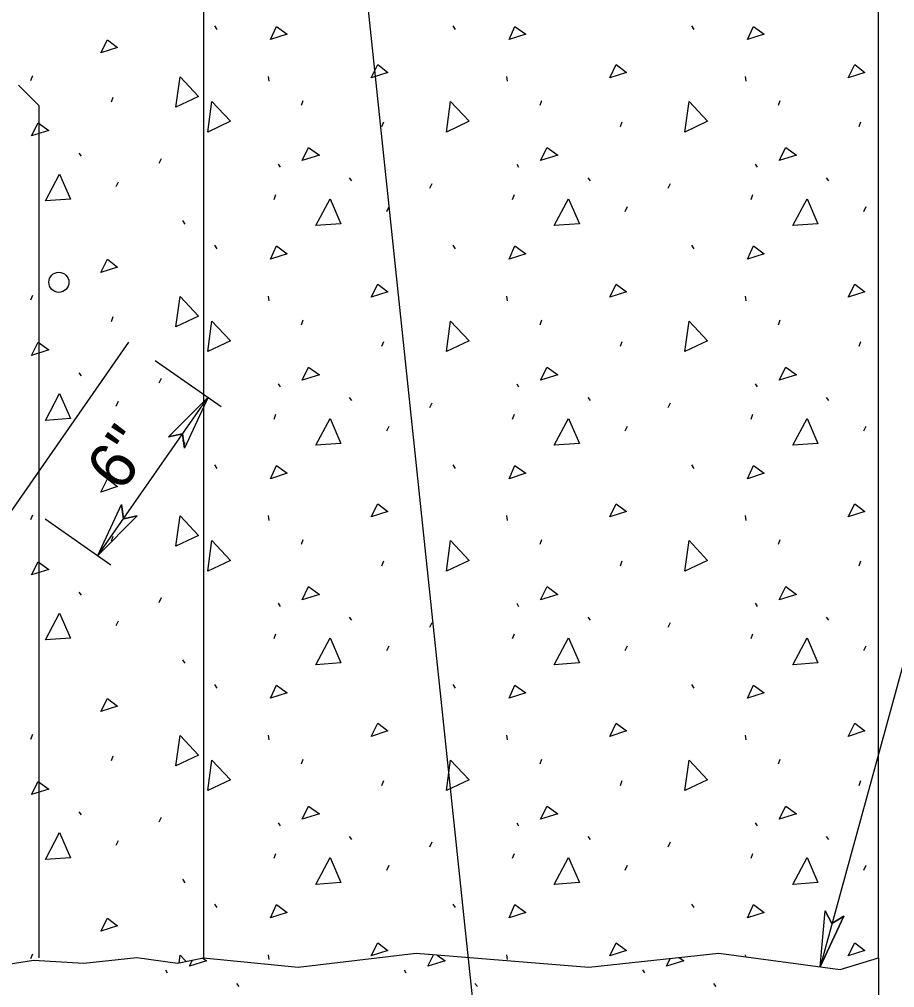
# Model space of a CAD drawing. Extents: x -26.5 to -19.2, y -3.6 to 6.6.
# Drawn here: x -23.351 to -22.216, y 1.707 to 2.961 of the extents above; entities that cross this region are included whole.
import ezdxf

# ---------------------------------------------------------------- set-up
doc = ezdxf.new("R2010")
doc.units = 0
for name, color, linetype in [('DETL-DIMS', 7, 'Continuous'), ('DETL-PATT', 7, 'Continuous'), ('Level 10', 7, 'Continuous'), ('Level 12', 7, 'Continuous'), ('SUBS-FOOT_P', 7, 'Continuous'), ('SUPR-RFRC', 7, 'Continuous')]:
    doc.layers.add(name, color=color, linetype=linetype)

msp = doc.modelspace()

# ---------------------------------------------------------------- linework, layer by layer
at = {"layer": 'DETL-DIMS'}
for p, q in [((-23.1061, 2.4717), (-23.1572, 2.4202)), ((-23.1061, 2.4717), (-23.1366, 2.4057)), ((-23.1572, 2.4202), (-23.1393, 2.4241)), ((-23.1393, 2.4241), (-23.1366, 2.4057)), ((-23.249, 2.2665), (-23.2185, 2.3325)), ((-23.2158, 2.3141), (-23.2185, 2.3325)), ((-23.249, 2.2665), (-23.1979, 2.318)), ((-23.1979, 2.318), (-23.2158, 2.3141)), ((-22.3128, 1.7338), (-22.3062, 1.8061)), ((-22.3128, 1.7338), (-22.2819, 1.7994)), ((-22.2975, 1.7897), (-22.3062, 1.8061)), ((-22.2819, 1.7994), (-22.2975, 1.7897))]:
    msp.add_line(p, q, dxfattribs=at)
for points in [[(-23.1572, 2.4202), (-23.1061, 2.4717), (-23.1366, 2.4057), (-23.1393, 2.4241)], [(-23.1979, 2.318), (-23.249, 2.2665), (-23.2185, 2.3325), (-23.2158, 2.3141)], [(-22.2819, 1.7994), (-22.3128, 1.7338), (-22.3062, 1.8061), (-22.2975, 1.7897)]]:
    msp.add_lwpolyline(points, close=True, dxfattribs=at)
at = {"layer": 'DETL-PATT'}
for p, q in [((-23.0979, 2.9528), (-23.0948, 2.9482)), ((-22.7887, 2.9528), (-22.7856, 2.9482)), ((-22.4795, 2.9528), (-22.4764, 2.9482)), ((-23.3356, 2.8821), (-23.3333, 2.8883)), ((-23.0283, 2.8871), (-23.0275, 2.8809)), ((-22.7191, 2.8871), (-22.7184, 2.8809)), ((-22.41, 2.8871), (-22.4092, 2.8809)), ((-23.2312, 2.8543), (-23.2289, 2.8605)), ((-22.985, 2.85), (-22.9827, 2.8562)), ((-22.6758, 2.85), (-22.6735, 2.8562)), ((-22.3667, 2.85), (-22.3644, 2.8562)), ((-22.8807, 2.8222), (-22.8784, 2.8284)), ((-22.5715, 2.8222), (-22.5692, 2.8284)), ((-22.2623, 2.8222), (-22.26, 2.8284)), ((-23.2737, 2.7879), (-23.2707, 2.784)), ((-23.1694, 2.7747), (-23.1663, 2.7809)), ((-23.0152, 2.7735), (-23.0128, 2.7696)), ((-22.706, 2.7735), (-22.7037, 2.7696)), ((-22.3968, 2.7735), (-22.3945, 2.7696)), ((-23.225, 2.7446), (-23.222, 2.7507)), ((-22.9232, 2.7557), (-22.9201, 2.7518)), ((-22.8188, 2.7426), (-22.8157, 2.7487)), ((-22.614, 2.7557), (-22.6109, 2.7518)), ((-22.5097, 2.7426), (-22.5066, 2.7487)), ((-22.3048, 2.7557), (-22.3017, 2.7518)), ((-23.0206, 2.7279), (-23.0183, 2.7341)), ((-22.7114, 2.7279), (-22.7091, 2.7341)), ((-22.4022, 2.7279), (-22.3999, 2.7341)), ((-22.8745, 2.7124), (-22.8714, 2.7186)), ((-22.5653, 2.7124), (-22.5622, 2.7186)), ((-22.2561, 2.7124), (-22.253, 2.7186)), ((-23.1393, 2.7005), (-23.1362, 2.6959)), ((-23.0979, 2.6684), (-23.0948, 2.6637)), ((-22.7887, 2.6684), (-22.7856, 2.6637)), ((-22.4795, 2.6684), (-22.4764, 2.6637)), ((-23.3356, 2.5977), (-23.3333, 2.6039)), ((-23.0283, 2.6027), (-23.0275, 2.5965)), ((-22.7191, 2.6027), (-22.7184, 2.5965)), ((-22.41, 2.6027), (-22.4092, 2.5965)), ((-23.2312, 2.5699), (-23.2289, 2.5761)), ((-22.985, 2.5656), (-22.9827, 2.5717)), ((-22.6758, 2.5656), (-22.6735, 2.5717)), ((-22.3667, 2.5656), (-22.3644, 2.5717)), ((-22.8807, 2.5377), (-22.8784, 2.5439)), ((-22.5715, 2.5377), (-22.5692, 2.5439)), ((-22.2623, 2.5377), (-22.26, 2.5439)), ((-23.2737, 2.5034), (-23.2707, 2.4995)), ((-23.1694, 2.4903), (-23.1663, 2.4965)), ((-23.0152, 2.489), (-23.0128, 2.4852)), ((-22.706, 2.489), (-22.7037, 2.4852)), ((-22.3968, 2.489), (-22.3945, 2.4852)), ((-22.9232, 2.4713), (-22.9201, 2.4674)), ((-22.614, 2.4713), (-22.6109, 2.4674)), ((-22.3048, 2.4713), (-22.3017, 2.4674)), ((-23.225, 2.4601), (-23.222, 2.4663)), ((-22.8188, 2.4581), (-22.8157, 2.4643)), ((-22.5097, 2.4581), (-22.5066, 2.4643)), ((-23.0206, 2.4434), (-23.0183, 2.4496)), ((-22.7114, 2.4434), (-22.7091, 2.4496)), ((-22.4022, 2.4434), (-22.3999, 2.4496)), ((-22.8745, 2.428), (-22.8714, 2.4342)), ((-22.5653, 2.428), (-22.5622, 2.4342)), ((-22.2561, 2.428), (-22.253, 2.4342)), ((-23.1393, 2.4161), (-23.1362, 2.4114)), ((-23.0979, 2.3839), (-23.0948, 2.3793)), ((-22.7887, 2.3839), (-22.7856, 2.3793)), ((-22.4795, 2.3839), (-22.4764, 2.3793)), ((-23.3356, 2.3133), (-23.3333, 2.3194)), ((-23.0283, 2.3182), (-23.0275, 2.312)), ((-22.7191, 2.3182), (-22.7184, 2.312)), ((-22.41, 2.3182), (-22.4092, 2.312)), ((-23.2312, 2.2854), (-23.2289, 2.2916)), ((-22.985, 2.2811), (-22.9827, 2.2873)), ((-22.6758, 2.2811), (-22.6735, 2.2873)), ((-22.3667, 2.2811), (-22.3644, 2.2873)), ((-22.8807, 2.2533), (-22.8784, 2.2595)), ((-22.5715, 2.2533), (-22.5692, 2.2595)), ((-22.2623, 2.2533), (-22.26, 2.2595)), ((-23.2737, 2.219), (-23.2707, 2.2151)), ((-23.1694, 2.2058), (-23.1663, 2.212)), ((-23.0152, 2.2046), (-23.0128, 2.2007)), ((-22.706, 2.2046), (-22.7037, 2.2007)), ((-22.3968, 2.2046), (-22.3945, 2.2007)), ((-22.9232, 2.1868), (-22.9201, 2.183)), ((-22.614, 2.1868), (-22.6109, 2.183)), ((-22.3048, 2.1868), (-22.3017, 2.183)), ((-23.225, 2.1757), (-23.222, 2.1819)), ((-22.8188, 2.1737), (-22.8157, 2.1799)), ((-22.5097, 2.1737), (-22.5066, 2.1799)), ((-23.0206, 2.159), (-23.0183, 2.1652)), ((-22.7114, 2.159), (-22.7091, 2.1652)), ((-22.4022, 2.159), (-22.3999, 2.1652)), ((-22.8745, 2.1435), (-22.8714, 2.1497)), ((-22.5653, 2.1435), (-22.5622, 2.1497)), ((-22.2561, 2.1435), (-22.253, 2.1497)), ((-23.1393, 2.1316), (-23.1362, 2.127)), ((-23.0979, 2.0995), (-23.0948, 2.0948)), ((-22.7887, 2.0995), (-22.7856, 2.0948)), ((-22.4795, 2.0995), (-22.4764, 2.0948)), ((-23.3356, 2.0288), (-23.3333, 2.035)), ((-23.0283, 2.0338), (-23.0275, 2.0276)), ((-22.7191, 2.0338), (-22.7184, 2.0276)), ((-22.41, 2.0338), (-22.4092, 2.0276)), ((-23.2312, 2.001), (-23.2289, 2.0072)), ((-22.985, 1.9967), (-22.9827, 2.0029)), ((-22.6758, 1.9967), (-22.6735, 2.0029)), ((-22.3667, 1.9967), (-22.3644, 2.0029)), ((-22.8807, 1.9688), (-22.8784, 1.975)), ((-22.5715, 1.9688), (-22.5692, 1.975)), ((-22.2623, 1.9688), (-22.26, 1.975)), ((-23.2737, 1.9345), (-23.2707, 1.9307)), ((-23.1694, 1.9214), (-23.1663, 1.9276)), ((-23.0152, 1.9202), (-23.0128, 1.9163)), ((-22.706, 1.9202), (-22.7037, 1.9163)), ((-22.3968, 1.9202), (-22.3945, 1.9163)), ((-23.225, 1.8912), (-23.222, 1.8974)), ((-22.9232, 1.9024), (-22.9201, 1.8985)), ((-22.8188, 1.8892), (-22.8157, 1.8954)), ((-22.614, 1.9024), (-22.6109, 1.8985)), ((-22.5097, 1.8892), (-22.5066, 1.8954)), ((-22.3048, 1.9024), (-22.3017, 1.8985)), ((-23.0206, 1.8746), (-23.0183, 1.8807)), ((-22.7114, 1.8746), (-22.7091, 1.8807)), ((-22.4022, 1.8746), (-22.3999, 1.8807)), ((-22.8745, 1.8591), (-22.8714, 1.8653)), ((-22.5653, 1.8591), (-22.5622, 1.8653)), ((-22.2561, 1.8591), (-22.253, 1.8653)), ((-23.1393, 1.8472), (-23.1362, 1.8425)), ((-23.0979, 1.815), (-23.0948, 1.8104)), ((-22.7887, 1.815), (-22.7856, 1.8104)), ((-22.4795, 1.815), (-22.4764, 1.8104)), ((-23.3356, 1.7444), (-23.3333, 1.7506)), ((-23.0283, 1.7493), (-23.0275, 1.7432)), ((-22.8211, 1.7345), (-22.8137, 1.7493)), ((-22.7191, 1.7493), (-22.7184, 1.7432)), ((-22.5119, 1.7345), (-22.507, 1.7444)), ((-22.41, 1.7493), (-22.4096, 1.7466)), ((-23.1303, 1.7345), (-23.1263, 1.7426)), ((-23.1612, 1.7299), (-23.1589, 1.726)), ((-22.852, 1.7299), (-22.8497, 1.726)), ((-22.5429, 1.7299), (-22.5405, 1.726)), ((-23.0692, 1.7121), (-23.0661, 1.7083)), ((-22.7601, 1.7121), (-22.757, 1.7083)), ((-22.4509, 1.7121), (-22.4478, 1.7083))]:
    msp.add_line(p, q, dxfattribs=at)
for points in [[(-23.0252, 2.935), (-23.0175, 2.952), (-23.0036, 2.942), (-23.0252, 2.935)], [(-22.716, 2.935), (-22.7083, 2.952), (-22.6944, 2.942), (-22.716, 2.935)], [(-22.4069, 2.935), (-22.3991, 2.952), (-22.3852, 2.942), (-22.4069, 2.935)], [(-23.2451, 2.9177), (-23.2366, 2.9347), (-23.2235, 2.9247), (-23.2451, 2.9177)], [(-22.8946, 2.8856), (-22.8861, 2.9026), (-22.8729, 2.8925), (-22.8946, 2.8856)], [(-22.5854, 2.8856), (-22.5769, 2.9026), (-22.5638, 2.8925), (-22.5854, 2.8856)], [(-22.2762, 2.8856), (-22.2677, 2.9026), (-22.2546, 2.8925), (-22.2762, 2.8856)], [(-23.1478, 2.8474), (-23.1423, 2.8868), (-23.1184, 2.8613), (-23.1478, 2.8474)], [(-23.1064, 2.8152), (-23.101, 2.8546), (-23.077, 2.8291), (-23.1064, 2.8152)], [(-22.7972, 2.8152), (-22.7918, 2.8546), (-22.7678, 2.8291), (-22.7972, 2.8152)], [(-22.488, 2.8152), (-22.4826, 2.8546), (-22.4586, 2.8291), (-22.488, 2.8152)], [(-23.3348, 2.8103), (-23.3263, 2.8273), (-23.3124, 2.8172), (-23.3348, 2.8103)], [(-22.9842, 2.7781), (-22.9757, 2.7951), (-22.9618, 2.7851), (-22.9842, 2.7781)], [(-22.6751, 2.7781), (-22.6666, 2.7951), (-22.6527, 2.7851), (-22.6751, 2.7781)], [(-22.3659, 2.7781), (-22.3574, 2.7951), (-22.3435, 2.7851), (-22.3659, 2.7781)], [(-23.317, 2.726), (-23.2985, 2.7608), (-23.2846, 2.7283), (-23.317, 2.726)], [(-22.9665, 2.6939), (-22.9479, 2.7286), (-22.934, 2.6962), (-22.9665, 2.6939)], [(-22.6573, 2.6939), (-22.6387, 2.7286), (-22.6248, 2.6962), (-22.6573, 2.6939)], [(-22.3481, 2.6939), (-22.3296, 2.7286), (-22.3157, 2.6962), (-22.3481, 2.6939)], [(-23.0252, 2.6506), (-23.0175, 2.6676), (-23.0036, 2.6575), (-23.0252, 2.6506)], [(-22.716, 2.6506), (-22.7083, 2.6676), (-22.6944, 2.6575), (-22.716, 2.6506)], [(-22.4069, 2.6506), (-22.3991, 2.6676), (-22.3852, 2.6575), (-22.4069, 2.6506)], [(-23.2451, 2.6333), (-23.2366, 2.6503), (-23.2235, 2.6402), (-23.2451, 2.6333)], [(-22.8946, 2.6011), (-22.8861, 2.6181), (-22.8729, 2.6081), (-22.8946, 2.6011)], [(-22.5854, 2.6011), (-22.5769, 2.6181), (-22.5638, 2.6081), (-22.5854, 2.6011)], [(-22.2762, 2.6011), (-22.2677, 2.6181), (-22.2546, 2.6081), (-22.2762, 2.6011)], [(-23.1478, 2.5629), (-23.1423, 2.6023), (-23.1184, 2.5768), (-23.1478, 2.5629)], [(-23.1064, 2.5308), (-23.101, 2.5702), (-23.077, 2.5447), (-23.1064, 2.5308)], [(-22.7972, 2.5308), (-22.7918, 2.5702), (-22.7678, 2.5447), (-22.7972, 2.5308)], [(-22.488, 2.5308), (-22.4826, 2.5702), (-22.4586, 2.5447), (-22.488, 2.5308)], [(-23.3348, 2.5258), (-23.3263, 2.5428), (-23.3124, 2.5328), (-23.3348, 2.5258)], [(-22.9842, 2.4937), (-22.9757, 2.5107), (-22.9618, 2.5006), (-22.9842, 2.4937)], [(-22.6751, 2.4937), (-22.6666, 2.5107), (-22.6527, 2.5006), (-22.6751, 2.4937)], [(-22.3659, 2.4937), (-22.3574, 2.5107), (-22.3435, 2.5006), (-22.3659, 2.4937)], [(-23.317, 2.4416), (-23.2985, 2.4764), (-23.2846, 2.4439), (-23.317, 2.4416)], [(-22.9665, 2.4094), (-22.9479, 2.4442), (-22.934, 2.4117), (-22.9665, 2.4094)], [(-22.6573, 2.4094), (-22.6387, 2.4442), (-22.6248, 2.4117), (-22.6573, 2.4094)], [(-22.3481, 2.4094), (-22.3296, 2.4442), (-22.3157, 2.4117), (-22.3481, 2.4094)], [(-23.0252, 2.3661), (-23.0175, 2.3831), (-23.0036, 2.3731), (-23.0252, 2.3661)], [(-22.716, 2.3661), (-22.7083, 2.3831), (-22.6944, 2.3731), (-22.716, 2.3661)], [(-22.4069, 2.3661), (-22.3991, 2.3831), (-22.3852, 2.3731), (-22.4069, 2.3661)], [(-23.2451, 2.3488), (-23.2366, 2.3658), (-23.2235, 2.3558), (-23.2451, 2.3488)], [(-22.8946, 2.3167), (-22.8861, 2.3337), (-22.8729, 2.3236), (-22.8946, 2.3167)], [(-22.5854, 2.3167), (-22.5769, 2.3337), (-22.5638, 2.3236), (-22.5854, 2.3167)], [(-22.2762, 2.3167), (-22.2677, 2.3337), (-22.2546, 2.3236), (-22.2762, 2.3167)], [(-23.1478, 2.2785), (-23.1423, 2.3179), (-23.1184, 2.2924), (-23.1478, 2.2785)], [(-23.1064, 2.2463), (-23.101, 2.2858), (-23.077, 2.2602), (-23.1064, 2.2463)], [(-22.7972, 2.2463), (-22.7918, 2.2858), (-22.7678, 2.2602), (-22.7972, 2.2463)], [(-22.488, 2.2463), (-22.4826, 2.2858), (-22.4586, 2.2602), (-22.488, 2.2463)], [(-23.3348, 2.2414), (-23.3263, 2.2584), (-23.3124, 2.2483), (-23.3348, 2.2414)], [(-22.9842, 2.2092), (-22.9757, 2.2262), (-22.9618, 2.2162), (-22.9842, 2.2092)], [(-22.6751, 2.2092), (-22.6666, 2.2262), (-22.6527, 2.2162), (-22.6751, 2.2092)], [(-22.3659, 2.2092), (-22.3574, 2.2262), (-22.3435, 2.2162), (-22.3659, 2.2092)], [(-23.317, 2.1571), (-23.2985, 2.1919), (-23.2846, 2.1594), (-23.317, 2.1571)], [(-22.9665, 2.125), (-22.9479, 2.1598), (-22.934, 2.1273), (-22.9665, 2.125)], [(-22.6573, 2.125), (-22.6387, 2.1598), (-22.6248, 2.1273), (-22.6573, 2.125)], [(-22.3481, 2.125), (-22.3296, 2.1598), (-22.3157, 2.1273), (-22.3481, 2.125)], [(-23.0252, 2.0817), (-23.0175, 2.0987), (-23.0036, 2.0887), (-23.0252, 2.0817)], [(-22.716, 2.0817), (-22.7083, 2.0987), (-22.6944, 2.0887), (-22.716, 2.0817)], [(-22.4069, 2.0817), (-22.3991, 2.0987), (-22.3852, 2.0887), (-22.4069, 2.0817)], [(-23.2451, 2.0644), (-23.2366, 2.0814), (-23.2235, 2.0713), (-23.2451, 2.0644)], [(-22.8946, 2.0322), (-22.8861, 2.0492), (-22.8729, 2.0392), (-22.8946, 2.0322)], [(-22.5854, 2.0322), (-22.5769, 2.0492), (-22.5638, 2.0392), (-22.5854, 2.0322)], [(-22.2762, 2.0322), (-22.2677, 2.0492), (-22.2546, 2.0392), (-22.2762, 2.0322)], [(-23.1478, 1.994), (-23.1423, 2.0335), (-23.1184, 2.008), (-23.1478, 1.994)], [(-23.1064, 1.9619), (-23.101, 2.0013), (-23.077, 1.9758), (-23.1064, 1.9619)], [(-22.7972, 1.9619), (-22.7918, 2.0013), (-22.7678, 1.9758), (-22.7972, 1.9619)], [(-22.488, 1.9619), (-22.4826, 2.0013), (-22.4586, 1.9758), (-22.488, 1.9619)], [(-23.3348, 1.9569), (-23.3263, 1.9739), (-23.3124, 1.9639), (-23.3348, 1.9569)], [(-22.9842, 1.9248), (-22.9757, 1.9418), (-22.9618, 1.9317), (-22.9842, 1.9248)], [(-22.6751, 1.9248), (-22.6666, 1.9418), (-22.6527, 1.9317), (-22.6751, 1.9248)], [(-22.3659, 1.9248), (-22.3574, 1.9418), (-22.3435, 1.9317), (-22.3659, 1.9248)], [(-23.317, 1.8727), (-23.2985, 1.9075), (-23.2846, 1.875), (-23.317, 1.8727)], [(-22.9665, 1.8405), (-22.9479, 1.8753), (-22.934, 1.8429), (-22.9665, 1.8405)], [(-22.6573, 1.8405), (-22.6387, 1.8753), (-22.6248, 1.8429), (-22.6573, 1.8405)], [(-22.3481, 1.8405), (-22.3296, 1.8753), (-22.3157, 1.8429), (-22.3481, 1.8405)], [(-23.0252, 1.7973), (-23.0175, 1.8143), (-23.0036, 1.8042), (-23.0252, 1.7973)], [(-22.716, 1.7973), (-22.7083, 1.8143), (-22.6944, 1.8042), (-22.716, 1.7973)], [(-22.4069, 1.7973), (-22.3991, 1.8143), (-22.3852, 1.8042), (-22.4069, 1.7973)], [(-23.2451, 1.7799), (-23.2366, 1.7969), (-23.2235, 1.7869), (-23.2451, 1.7799)], [(-22.8946, 1.7478), (-22.8861, 1.7648), (-22.8729, 1.7547), (-22.8946, 1.7478)], [(-22.5854, 1.7478), (-22.5769, 1.7648), (-22.5638, 1.7547), (-22.5854, 1.7478)], [(-22.2762, 1.7478), (-22.2677, 1.7648), (-22.2546, 1.7547), (-22.2762, 1.7478)], [(-23.1437, 1.739), (-23.1423, 1.749), (-23.1347, 1.7409)], [(-23.1131, 1.7453), (-23.1079, 1.7415), (-23.1303, 1.7345)], [(-22.809, 1.749), (-22.7987, 1.7415), (-22.8211, 1.7345)], [(-22.4953, 1.7457), (-22.4895, 1.7415), (-22.5119, 1.7345)]]:
    msp.add_lwpolyline(points, dxfattribs=at)
at = {"layer": 'Level 10'}
for p, q in [((-23.1746, 2.5193), (-23.0891, 2.4598)), ((-23.249, 2.2665), (-23.1061, 2.4717)), ((-22.149, 2.3306), (-22.3128, 1.7338)), ((-23.3174, 2.3142), (-23.2319, 2.2546))]:
    msp.add_line(p, q, dxfattribs=at)
at = {"layer": 'SUBS-FOOT_P'}
for p, q in [((-23.112, 3.7455), (-23.112, 1.7455)), ((-22.237, 1.7455), (-22.237, 3.7455)), ((-22.237, 1.7455), (-22.237, 0.7455))]:
    msp.add_line(p, q, dxfattribs=at)
for points in [[(-23.3653, 1.7373), (-23.3322, 1.7421), (-23.2672, 1.7383), (-23.1984, 1.7457), (-23.1457, 1.7386), (-23.112, 1.7455)], [(-23.112, 1.7455), (-22.9895, 1.7331), (-22.8364, 1.7512), (-22.6124, 1.7331), (-22.444, 1.7512), (-22.2867, 1.7303), (-22.237, 1.7455)]]:
    msp.add_lwpolyline(points, dxfattribs=at)
at = {"layer": 'SUPR-RFRC'}
for p, q in [((-23.0958, 4.8436), (-22.6767, 0.8705)), ((-23.3255, 2.8497), (-23.3516, 2.8757)), ((-23.3255, 2.8497), (-23.3255, 1.7455)), ((-23.6813, 1.8645), (-23.2087, 2.5431))]:
    msp.add_line(p, q, dxfattribs=at)
msp.add_circle((-23.2995, 2.6205), 0.013, dxfattribs=at)

# ---------------------------------------------------------------- texts
at = {"layer": 'Level 12'}
msp.add_text('6"', height=0.06001, rotation=55.1498, dxfattribs=at).set_placement((-23.2182, 2.3471))

doc.saveas('drawing.dxf')
